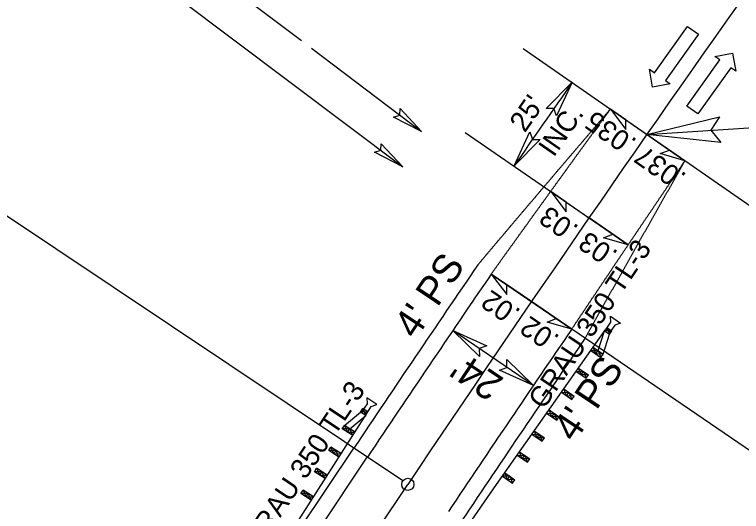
# Model space of a CAD drawing. Extents: x 1716813 to 1718091, y 800228 to 801730.
# Drawn here: x 1717558 to 1717736.9, y 801205.8 to 801328.1 of the extents above; entities that cross this region are included whole.
import ezdxf

# ---------------------------------------------------------------- set-up
doc = ezdxf.new("R2010")
doc.units = 0
for name, color, linetype in [('Prop Dimension', 7, 'Continuous'), ('Prop DSN Text', 7, 'Continuous'), ('Prop EOT', 7, 'Continuous'), ('Prop Guardrail', 7, 'Continuous'), ('Prop Guardrail Anchor Unit CELL', 7, 'Continuous'), ('Prop Horizontal Alignment', 7, 'Continuous'), ('Prop Horizontal Alignment Station Label', 7, 'Continuous'), ('Prop Horizontal Alignment Tick Large', 7, 'Continuous'), ('Prop Lane Arrow CELL', 7, 'Continuous'), ('Prop Paved Shoulder', 7, 'Continuous'), ('Prop Superelevation  Arrow CELL', 7, 'Continuous'), ('Prop Superelevation Label', 7, 'Continuous'), ('Prop Terminator CELL', 7, 'Continuous')]:
    doc.layers.add(name, color=color, linetype=linetype)

msp = doc.modelspace()

# ---------------------------------------------------------------- linework, layer by layer
at = {"layer": 'Prop Dimension'}
for p, q in [((1717683.22, 801319.8), (1717704.66, 801304.87)), ((1717713.62, 801298.64), (1717924.42, 801311.93)), ((1717668.93, 801299.09), (1717689.95, 801284.59)), ((1717787.77, 801247.02), (1717723, 801292.11)), ((1717685.71, 801236.85), (1717665.85, 801250.33)), ((1717759.65, 801206.63), (1717695.14, 801250.71))]:
    msp.add_line(p, q, dxfattribs=at)
msp.add_arc((1722422.94, 798021.12), 5760, 145.162498, 145.41239, dxfattribs=at)
at = {"layer": 'Prop DSN Text'}
for p, q in [((1717594.17, 801335.36), (1717653.56, 801290.68)), ((1717614.37, 801332.47), (1717628.62, 801321.71)), ((1717631.1, 801319.83), (1717658.21, 801299.35))]:
    msp.add_line(p, q, dxfattribs=at)
at = {"layer": 'Prop EOT'}
msp.add_line((1717496.5, 800997.53), (1717644.84, 801219.17), dxfattribs=at)
for radius in [5712, 5688]:
    msp.add_arc((1722391.71, 798042.03), radius, 145.65923, 146.20506, dxfattribs=at)
for points in [[(1717675.33, 801264.24), (1717675.72, 801264.79), (1717676.11, 801265.35), (1717676.51, 801265.9), (1717676.9, 801266.45), (1717677.3, 801267), (1717677.69, 801267.55), (1717678.09, 801268.1), (1717678.48, 801268.65), (1717678.87, 801269.2), (1717679.27, 801269.75), (1717679.66, 801270.3), (1717680.06, 801270.85), (1717680.45, 801271.4), (1717680.85, 801271.95), (1717681.24, 801272.5), (1717681.64, 801273.05), (1717682.03, 801273.6), (1717682.43, 801274.15), (1717682.82, 801274.7), (1717683.22, 801275.25), (1717683.61, 801275.8), (1717684.01, 801276.35), (1717684.41, 801276.9), (1717684.8, 801277.45), (1717685.2, 801278), (1717685.59, 801278.55), (1717685.99, 801279.1), (1717686.38, 801279.65), (1717686.78, 801280.2), (1717687.18, 801280.75), (1717687.57, 801281.3), (1717687.97, 801281.85), (1717688.36, 801282.39), (1717688.76, 801282.94), (1717689.16, 801283.49), (1717689.55, 801284.04), (1717689.95, 801284.59), (1717690.35, 801285.14), (1717690.74, 801285.69), (1717691.14, 801286.24), (1717691.54, 801286.79), (1717691.93, 801287.34), (1717692.33, 801287.88), (1717692.73, 801288.43), (1717693.12, 801288.98), (1717693.52, 801289.53), (1717693.92, 801290.08), (1717694.31, 801290.63), (1717694.71, 801291.18), (1717695.11, 801291.72), (1717695.51, 801292.27), (1717695.9, 801292.82), (1717696.3, 801293.37), (1717696.7, 801293.92), (1717697.1, 801294.47), (1717697.49, 801295.01), (1717697.89, 801295.56), (1717698.29, 801296.11), (1717698.69, 801296.66), (1717699.08, 801297.21), (1717699.48, 801297.75), (1717699.88, 801298.3), (1717700.28, 801298.85), (1717700.68, 801299.4), (1717701.07, 801299.94), (1717701.47, 801300.49), (1717701.87, 801301.04), (1717702.27, 801301.59), (1717702.67, 801302.13), (1717703.07, 801302.68), (1717703.47, 801303.23), (1717703.86, 801303.78), (1717704.66, 801304.87)], [(1717695.14, 801250.71), (1717695.52, 801251.27), (1717695.89, 801251.83), (1717696.26, 801252.39), (1717696.64, 801252.95), (1717697.01, 801253.51), (1717697.39, 801254.07), (1717697.76, 801254.63), (1717698.14, 801255.19), (1717698.51, 801255.75), (1717698.88, 801256.31), (1717699.26, 801256.87), (1717699.63, 801257.44), (1717700.01, 801258), (1717700.38, 801258.56), (1717700.76, 801259.12), (1717701.13, 801259.68), (1717701.51, 801260.24), (1717701.88, 801260.8), (1717702.26, 801261.36), (1717702.63, 801261.92), (1717703.01, 801262.48), (1717703.39, 801263.04), (1717703.76, 801263.6), (1717704.14, 801264.16), (1717704.51, 801264.72), (1717704.89, 801265.28), (1717705.26, 801265.84), (1717705.64, 801266.4), (1717706.01, 801266.96), (1717706.39, 801267.52), (1717706.77, 801268.08), (1717707.14, 801268.64), (1717707.52, 801269.2), (1717707.89, 801269.76), (1717708.27, 801270.32), (1717708.65, 801270.88), (1717709.02, 801271.44), (1717709.4, 801272), (1717709.78, 801272.56), (1717710.15, 801273.11), (1717710.53, 801273.67), (1717710.91, 801274.23), (1717711.28, 801274.79), (1717711.66, 801275.35), (1717712.04, 801275.91), (1717712.41, 801276.47), (1717712.79, 801277.03), (1717713.17, 801277.59), (1717713.55, 801278.15), (1717713.92, 801278.71), (1717714.3, 801279.26), (1717714.68, 801279.82), (1717715.06, 801280.38), (1717715.43, 801280.94), (1717715.81, 801281.5), (1717716.19, 801282.06), (1717716.57, 801282.62), (1717716.94, 801283.18), (1717717.32, 801283.73), (1717717.7, 801284.29), (1717718.08, 801284.85), (1717718.46, 801285.41), (1717718.83, 801285.97), (1717719.21, 801286.53), (1717719.59, 801287.08), (1717719.97, 801287.64), (1717720.35, 801288.2), (1717720.72, 801288.76), (1717721.1, 801289.32), (1717721.48, 801289.88), (1717721.86, 801290.43), (1717722.24, 801290.99), (1717723, 801292.11)]]:
    msp.add_spline(points, degree=3, dxfattribs=at)
at = {"layer": 'Prop Guardrail'}
msp.add_line((1717640.85, 801161.21), (1717676.64, 801212.44), dxfattribs=at)
at = {"layer": 'Prop Guardrail Anchor Unit CELL'}
for p, q in [((1717704.72, 801252.39), (1717704.67, 801253.85)), ((1717704.67, 801253.85), (1717707.11, 801252.2)), ((1717703.58, 801250.69), (1717704.72, 801252.39)), ((1717705.74, 801251.7), (1717704.59, 801250.01)), ((1717707.11, 801252.2), (1717705.74, 801251.7)), ((1717676.64, 801212.44), (1717703.5, 801250.71)), ((1717701.65, 801245.41), (1717703.21, 801250.3)), ((1717703.21, 801250.3), (1717704.44, 801249.44)), ((1717705.01, 801250.26), (1717703.21, 801250.3)), ((1717704.09, 801250.35), (1717703.58, 801250.69)), ((1717703.79, 801251.12), (1717705.01, 801250.26)), ((1717703.79, 801251.12), (1717704.44, 801249.44)), ((1717704.59, 801250.01), (1717704.09, 801250.35)), ((1717704.44, 801249.44), (1717705.01, 801250.26)), ((1717704.44, 801249.44), (1717704.73, 801249.85)), ((1717702.9, 801244.53), (1717704.44, 801249.44)), ((1717700.4, 801246.29), (1717702.9, 801244.53)), ((1717701.08, 801244.59), (1717700.4, 801246.29)), ((1717699.82, 801245.47), (1717702.33, 801243.71)), ((1717699.82, 801245.47), (1717701.65, 801245.41)), ((1717701.08, 801244.59), (1717701.65, 801245.41)), ((1717702.9, 801244.53), (1717701.08, 801244.59)), ((1717701.65, 801245.41), (1717702.33, 801243.71)), ((1717702.33, 801243.71), (1717702.9, 801244.53)), ((1717696.78, 801241.13), (1717699.23, 801239.41)), ((1717697.43, 801239.45), (1717696.78, 801241.13)), ((1717696.2, 801240.31), (1717698.66, 801238.59)), ((1717696.2, 801240.31), (1717698, 801240.27)), ((1717697.43, 801239.45), (1717698, 801240.27)), ((1717699.23, 801239.41), (1717697.43, 801239.45)), ((1717698, 801240.27), (1717698.66, 801238.59)), ((1717698.66, 801238.59), (1717699.23, 801239.41)), ((1717693.16, 801235.97), (1717695.72, 801234.17)), ((1717693.87, 801234.25), (1717693.16, 801235.97)), ((1717647.19, 801232.17), (1717644.74, 801233.8)), ((1717644.74, 801233.8), (1717644.8, 801232.34)), ((1717692.58, 801235.15), (1717695.15, 801233.35)), ((1717692.58, 801235.15), (1717694.44, 801235.07)), ((1717693.87, 801234.25), (1717694.44, 801235.07)), ((1717695.72, 801234.17), (1717693.87, 801234.25)), ((1717694.44, 801235.07), (1717695.15, 801233.35)), ((1717695.15, 801233.35), (1717695.72, 801234.17)), ((1717644.8, 801232.34), (1717643.66, 801230.64)), ((1717645.82, 801231.67), (1717647.19, 801232.17)), ((1717639.23, 801227.01), (1717643.19, 801230.29)), ((1717643.19, 801230.29), (1717643.73, 801231.13)), ((1717643.19, 801230.29), (1717643.46, 801230.71)), ((1717645, 801230.32), (1717643.19, 801230.29)), ((1717644.46, 801229.48), (1717643.19, 801230.29)), ((1717643.66, 801230.64), (1717644.17, 801230.3)), ((1717645, 801230.32), (1717643.73, 801231.13)), ((1717643.73, 801231.13), (1717644.46, 801229.48)), ((1717644.17, 801230.3), (1717644.68, 801229.96)), ((1717644.68, 801229.96), (1717645.82, 801231.67)), ((1717688.96, 801230), (1717689.54, 801230.82)), ((1717689.54, 801230.82), (1717692.02, 801229.07)), ((1717690.21, 801229.13), (1717689.54, 801230.82)), ((1717619.47, 801190.55), (1717644.73, 801229.9)), ((1717640.52, 801226.18), (1717644.46, 801229.48)), ((1717688.96, 801230), (1717691.45, 801228.25)), ((1717688.96, 801230), (1717690.78, 801229.94)), ((1717690.21, 801229.13), (1717690.78, 801229.94)), ((1717692.02, 801229.07), (1717690.21, 801229.13)), ((1717690.78, 801229.94), (1717691.45, 801228.25)), ((1717691.45, 801228.25), (1717692.02, 801229.07)), ((1717638.69, 801226.16), (1717639.23, 801227.01)), ((1717641.81, 801225.35), (1717639.23, 801227.01)), ((1717639.23, 801227.01), (1717639.98, 801225.34)), ((1717640.52, 801226.18), (1717638.69, 801226.16)), ((1717641.27, 801224.51), (1717638.69, 801226.16)), ((1717639.98, 801225.34), (1717640.52, 801226.18)), ((1717639.98, 801225.34), (1717641.81, 801225.35)), ((1717641.27, 801224.51), (1717640.52, 801226.18)), ((1717685.34, 801224.84), (1717687.84, 801223.09)), ((1717685.34, 801224.84), (1717687.16, 801224.78)), ((1717685.92, 801225.66), (1717688.41, 801223.91)), ((1717686.59, 801223.96), (1717685.92, 801225.66)), ((1717686.59, 801223.96), (1717687.16, 801224.78)), ((1717687.16, 801224.78), (1717687.84, 801223.09)), ((1717688.41, 801223.91), (1717686.59, 801223.96)), ((1717687.84, 801223.09), (1717688.41, 801223.91)), ((1717635.34, 801220.83), (1717635.88, 801221.67)), ((1717638.41, 801220.05), (1717635.88, 801221.67)), ((1717635.88, 801221.67), (1717636.6, 801220.02)), ((1717637.14, 801220.86), (1717635.34, 801220.83)), ((1717637.87, 801219.21), (1717635.34, 801220.83)), ((1717636.6, 801220.02), (1717637.14, 801220.86)), ((1717636.6, 801220.02), (1717638.41, 801220.05)), ((1717637.87, 801219.21), (1717637.14, 801220.86)), ((1717681.72, 801219.68), (1717684.22, 801217.93)), ((1717681.72, 801219.68), (1717683.55, 801219.62)), ((1717682.3, 801220.5), (1717684.8, 801218.75)), ((1717682.97, 801218.81), (1717682.3, 801220.5)), ((1717682.97, 801218.81), (1717683.55, 801219.62)), ((1717683.55, 801219.62), (1717684.22, 801217.93)), ((1717684.8, 801218.75), (1717682.97, 801218.81)), ((1717684.22, 801217.93), (1717684.8, 801218.75)), ((1717631.82, 801215.6), (1717632.36, 801216.44)), ((1717635, 801214.75), (1717632.36, 801216.44)), ((1717632.36, 801216.44), (1717633.14, 801214.75)), ((1717634.46, 801213.9), (1717631.82, 801215.6)), ((1717633.68, 801215.59), (1717631.82, 801215.6)), ((1717633.14, 801214.75), (1717633.68, 801215.59)), ((1717633.14, 801214.75), (1717635, 801214.75)), ((1717634.46, 801213.9), (1717633.68, 801215.59)), ((1717678.1, 801214.52), (1717678.68, 801215.34)), ((1717678.1, 801214.52), (1717680.56, 801212.8)), ((1717679.91, 801214.48), (1717678.1, 801214.52)), ((1717678.68, 801215.34), (1717681.13, 801213.62)), ((1717678.68, 801215.34), (1717679.91, 801214.48)), ((1717679.33, 801213.66), (1717678.68, 801215.34)), ((1717679.33, 801213.66), (1717679.91, 801214.48)), ((1717679.91, 801214.48), (1717680.56, 801212.8)), ((1717681.13, 801213.62), (1717679.33, 801213.66)), ((1717680.56, 801212.8), (1717681.13, 801213.62)), ((1717628.5, 801210.24), (1717629.04, 801211.08)), ((1717631.6, 801209.44), (1717629.04, 801211.08)), ((1717629.04, 801211.08), (1717629.78, 801209.42)), ((1717630.32, 801210.26), (1717628.5, 801210.24)), ((1717631.06, 801208.6), (1717628.5, 801210.24)), ((1717629.78, 801209.42), (1717630.32, 801210.26)), ((1717629.78, 801209.42), (1717631.6, 801209.44)), ((1717631.06, 801208.6), (1717630.32, 801210.26)), ((1717631.06, 801208.6), (1717631.6, 801209.44))]:
    msp.add_line(p, q, dxfattribs=at)
at = {"layer": 'Prop Horizontal Alignment'}
msp.add_line((1717404.5, 800838.5), (1717654.82, 801212.49), dxfattribs=at)
msp.add_arc((1722391.71, 798042.03), 5700, 144.61167, 146.20506, dxfattribs=at)
at = {"layer": 'Prop Horizontal Alignment Station Label'}
msp.add_line((1717653.57, 801213.33), (1717426.28, 801365.45), dxfattribs=at)
msp.add_circle((1717654.82, 801212.49), 1.5, dxfattribs=at)
at = {"layer": 'Prop Horizontal Alignment Tick Large'}
msp.add_line((1717685.23, 801257.47), (1717678.63, 801261.99), dxfattribs=at)
at = {"layer": 'Prop Lane Arrow CELL'}
for p, q in [((1717715.48, 801313.82), (1717723.62, 801325.22)), ((1717723.62, 801325.22), (1717726.3, 801323.3)), ((1717726.3, 801323.3), (1717718.17, 801311.91)), ((1717730.35, 801317.83), (1717734.7, 801318.59)), ((1717731.57, 801316.96), (1717730.35, 801317.83)), ((1717734.7, 801318.59), (1717735.47, 801314.17)), ((1717723.43, 801305.56), (1717731.57, 801316.96)), ((1717715.04, 801310.27), (1717714.26, 801314.7)), ((1717714.26, 801314.7), (1717715.48, 801313.82)), ((1717734.25, 801315.04), (1717726.12, 801303.65)), ((1717735.47, 801314.17), (1717734.25, 801315.04)), ((1717719.39, 801311.04), (1717715.04, 801310.27)), ((1717718.17, 801311.91), (1717719.39, 801311.04)), ((1717726.12, 801303.65), (1717723.43, 801305.56))]:
    msp.add_line(p, q, dxfattribs=at)
at = {"layer": 'Prop Paved Shoulder'}
msp.add_line((1717627.97, 801201.14), (1717641.52, 801221.39), dxfattribs=at)
for radius in [5716, 5684]:
    msp.add_arc((1722391.71, 798042.03), radius, 145.65923, 146.20506, dxfattribs=at)
for points in [[(1717672.02, 801266.5), (1717672.46, 801267.02), (1717672.9, 801267.54), (1717673.34, 801268.06), (1717673.78, 801268.58), (1717674.22, 801269.1), (1717674.66, 801269.62), (1717675.1, 801270.14), (1717675.54, 801270.66), (1717675.98, 801271.18), (1717676.41, 801271.7), (1717676.85, 801272.22), (1717677.29, 801272.74), (1717677.73, 801273.26), (1717678.17, 801273.78), (1717678.61, 801274.3), (1717679.05, 801274.82), (1717679.49, 801275.34), (1717679.93, 801275.86), (1717680.37, 801276.38), (1717680.81, 801276.9), (1717681.25, 801277.42), (1717681.69, 801277.94), (1717682.13, 801278.46), (1717682.57, 801278.98), (1717683.01, 801279.5), (1717683.45, 801280.02), (1717683.9, 801280.54), (1717684.34, 801281.06), (1717684.78, 801281.58), (1717685.22, 801282.1), (1717685.66, 801282.61), (1717686.1, 801283.13), (1717686.54, 801283.65), (1717686.98, 801284.17), (1717687.42, 801284.69), (1717687.86, 801285.21), (1717688.3, 801285.73), (1717688.74, 801286.24), (1717689.19, 801286.76), (1717689.63, 801287.28), (1717690.07, 801287.8), (1717690.51, 801288.32), (1717690.95, 801288.84), (1717691.39, 801289.35), (1717691.83, 801289.87), (1717692.27, 801290.39), (1717692.72, 801290.91), (1717693.16, 801291.43), (1717693.6, 801291.94), (1717694.04, 801292.46), (1717694.48, 801292.98), (1717694.93, 801293.5), (1717695.37, 801294.02), (1717695.81, 801294.53), (1717696.25, 801295.05), (1717696.69, 801295.57), (1717697.14, 801296.09), (1717697.58, 801296.6), (1717698.02, 801297.12), (1717698.46, 801297.64), (1717698.91, 801298.15), (1717699.35, 801298.67), (1717699.79, 801299.19), (1717700.23, 801299.71), (1717700.68, 801300.22), (1717701.12, 801300.74), (1717701.56, 801301.26), (1717702, 801301.77), (1717702.45, 801302.29), (1717702.89, 801302.81), (1717703.33, 801303.32), (1717703.78, 801303.84), (1717704.66, 801304.87)], [(1717698.44, 801248.45), (1717698.77, 801249.04), (1717699.1, 801249.63), (1717699.43, 801250.22), (1717699.76, 801250.81), (1717700.09, 801251.4), (1717700.42, 801252), (1717700.75, 801252.59), (1717701.08, 801253.18), (1717701.41, 801253.77), (1717701.74, 801254.36), (1717702.07, 801254.95), (1717702.4, 801255.54), (1717702.73, 801256.13), (1717703.06, 801256.72), (1717703.39, 801257.31), (1717703.72, 801257.9), (1717704.05, 801258.49), (1717704.38, 801259.09), (1717704.71, 801259.68), (1717705.04, 801260.27), (1717705.37, 801260.86), (1717705.7, 801261.45), (1717706.03, 801262.04), (1717706.36, 801262.63), (1717706.69, 801263.22), (1717707.03, 801263.81), (1717707.36, 801264.4), (1717707.69, 801264.99), (1717708.02, 801265.58), (1717708.35, 801266.17), (1717708.68, 801266.76), (1717709.01, 801267.35), (1717709.34, 801267.94), (1717709.68, 801268.53), (1717710.01, 801269.12), (1717710.34, 801269.71), (1717710.67, 801270.3), (1717711, 801270.89), (1717711.33, 801271.48), (1717711.67, 801272.07), (1717712, 801272.66), (1717712.33, 801273.25), (1717712.66, 801273.84), (1717712.99, 801274.43), (1717713.33, 801275.02), (1717713.66, 801275.61), (1717713.99, 801276.2), (1717714.32, 801276.79), (1717714.66, 801277.38), (1717714.99, 801277.97), (1717715.32, 801278.56), (1717715.66, 801279.15), (1717715.99, 801279.74), (1717716.32, 801280.33), (1717716.65, 801280.92), (1717716.99, 801281.5), (1717717.32, 801282.09), (1717717.65, 801282.68), (1717717.99, 801283.27), (1717718.32, 801283.86), (1717718.65, 801284.45), (1717718.99, 801285.04), (1717719.32, 801285.63), (1717719.66, 801286.22), (1717719.99, 801286.81), (1717720.32, 801287.4), (1717720.66, 801287.99), (1717720.99, 801288.57), (1717721.33, 801289.16), (1717721.66, 801289.75), (1717721.99, 801290.34), (1717722.33, 801290.93), (1717723, 801292.11)]]:
    msp.add_spline(points, degree=3, dxfattribs=at)
at = {"layer": 'Prop Superelevation  Arrow CELL'}
for p, q in [((1717704.66, 801304.87), (1717714.51, 801298.02)), ((1717723, 801292.11), (1717713.15, 801298.96)), ((1717689.95, 801284.59), (1717699.83, 801277.78)), ((1717709.02, 801271.44), (1717699.15, 801278.25)), ((1717675.33, 801264.24), (1717685.23, 801257.47)), ((1717695.14, 801250.71), (1717685.23, 801257.47))]:
    msp.add_line(p, q, dxfattribs=at)
for points in [[(1717704.66, 801304.87), (1717708.44, 801299.8), (1717708.46, 801302.23)], [(1717723, 801292.11), (1717716.93, 801293.89), (1717719.2, 801294.75)], [(1717689.95, 801284.59), (1717693.75, 801279.54), (1717693.76, 801281.97)], [(1717709.02, 801271.44), (1717702.95, 801273.2), (1717705.22, 801274.06)], [(1717675.33, 801264.24), (1717679.15, 801259.21), (1717679.14, 801261.63)], [(1717695.14, 801250.71), (1717689.06, 801252.44), (1717691.32, 801253.31)]]:
    msp.add_lwpolyline(points, close=True, dxfattribs=at)
at = {"layer": 'Prop Superelevation Label'}
for p, q in [((1717704.66, 801304.87), (1717723, 801292.11)), ((1717689.95, 801284.59), (1717709.02, 801271.44)), ((1717675.33, 801264.24), (1717695.14, 801250.71))]:
    msp.add_line(p, q, dxfattribs=at)
at = {"layer": 'Prop Terminator CELL'}
for points in [[(1717688.86, 801305.02), (1717695.28, 801311.52), (1717691.42, 801303.18), (1717690.76, 801305.04)], [(1717652.9, 801305.01), (1717658.21, 801299.35), (1717651.26, 801302.9), (1717652.85, 801303.4)], [(1717652.9, 801305.01), (1717658.21, 801299.35), (1717651.26, 801302.9), (1717652.85, 801303.4)], [(1717731.78, 801296.67), (1717713.62, 801298.64), (1717731.48, 801302.97), (1717729.39, 801299.63)], [(1717687.36, 801297.4), (1717680.97, 801290.87), (1717684.79, 801299.23), (1717685.46, 801297.38)], [(1717648.24, 801296.33), (1717653.56, 801290.68), (1717646.6, 801294.22), (1717648.2, 801294.72)], [(1717672.43, 801244), (1717665.85, 801250.33), (1717674.24, 801246.58), (1717672.39, 801245.9)], [(1717679.13, 801243.19), (1717685.71, 801236.85), (1717677.32, 801240.61), (1717679.17, 801241.29)]]:
    msp.add_lwpolyline(points, close=True, dxfattribs=at)

# ---------------------------------------------------------------- texts
at = {"layer": 'Prop Dimension'}
for s, height, rotation, p in [("25'", 5, 55.2823, (1717683.6, 801298.85)), ('INC.', 5, 55.2823, (1717690.7, 801292.82)), ("4' PS", 7, 56.2051, (1717656.76, 801247.95)), ("24'", 7, 146.2051, (1717678.74, 801238.44)), ("4' PS", 7, 56.2051, (1717695.87, 801222.58))]:
    msp.add_text(s, height=height, rotation=rotation, dxfattribs=at).set_placement(p)
at = {"layer": 'Prop Guardrail Anchor Unit CELL'}
for p in [(1717688.26, 801230.71), (1717617.83, 801195.86)]:
    msp.add_text('GRAU 350 TL-3', height=5, rotation=56.2051, dxfattribs=at).set_placement(p)
at = {"layer": 'Prop Superelevation Label'}
for s, rotation, p in [('.035', 145.1566, (1717711.43, 801297.25)), ('.037', 145.1566, (1717723.63, 801288.74)), ('.03', 145.1566, (1717697.12, 801275.93)), ('.03', 145.1566, (1717706.78, 801269.67)), ('.02', 145.6592, (1717682.86, 801255.32)), ('.02', 145.6592, (1717692.43, 801248.91))]:
    msp.add_text(s, height=5, rotation=rotation, dxfattribs=at).set_placement(p)

doc.saveas('drawing.dxf')
